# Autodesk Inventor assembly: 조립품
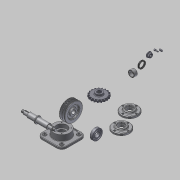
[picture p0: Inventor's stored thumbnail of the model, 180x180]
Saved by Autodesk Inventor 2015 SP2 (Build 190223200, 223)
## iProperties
Created: 2015-07
Part Number: 조립품
Document SubType Name: Assembly
Designer: AMC
Author: AMC
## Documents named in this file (12)
- C:\Users\AMC\Desktop\450735V1005\조립품.iam
- C:\Users\AMC\Desktop\450735V1005\본체.ipt
- C:\Users\AMC\Desktop\450735V1005\2-커버.ipt
- C:\Users\AMC\Desktop\450735V1005\3-축.ipt
- C:\Users\AMC\Desktop\450735V1005\4-V벨트풀리.ipt
- C:\Users\AMC\Desktop\450735V1005\5-체인 스프로킷.ipt
- C:\Users\AMC\Desktop\450735V1005\6-베어링 6206.ipt
- C:\Users\AMC\Desktop\450735V1005\7-부시.ipt
- C:\Users\AMC\Desktop\450735V1005\8-오일실 30x42.ipt
- C:\Users\AMC\Desktop\450735V1005\9-M16-너트.ipt
- C:\Users\AMC\Desktop\450735V1005\10-M6.ipt
- C:\Users\AMC\Desktop\450735V1005\11-키 6x6.ipt
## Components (11 placed, 10 different names)
1. 3-축:1
2. 4-V벨트풀리:1
3. 5-체인 스프로킷:1
4. 6-베어링 6206:1
5. 7-부시:1
6. 8-8-오일실 30x42:1
7. 9-M16 너트:1
8. 10-M6:1
9. 11-키 6x6:1
10. 2-커버:1
11. 2-커버:2
